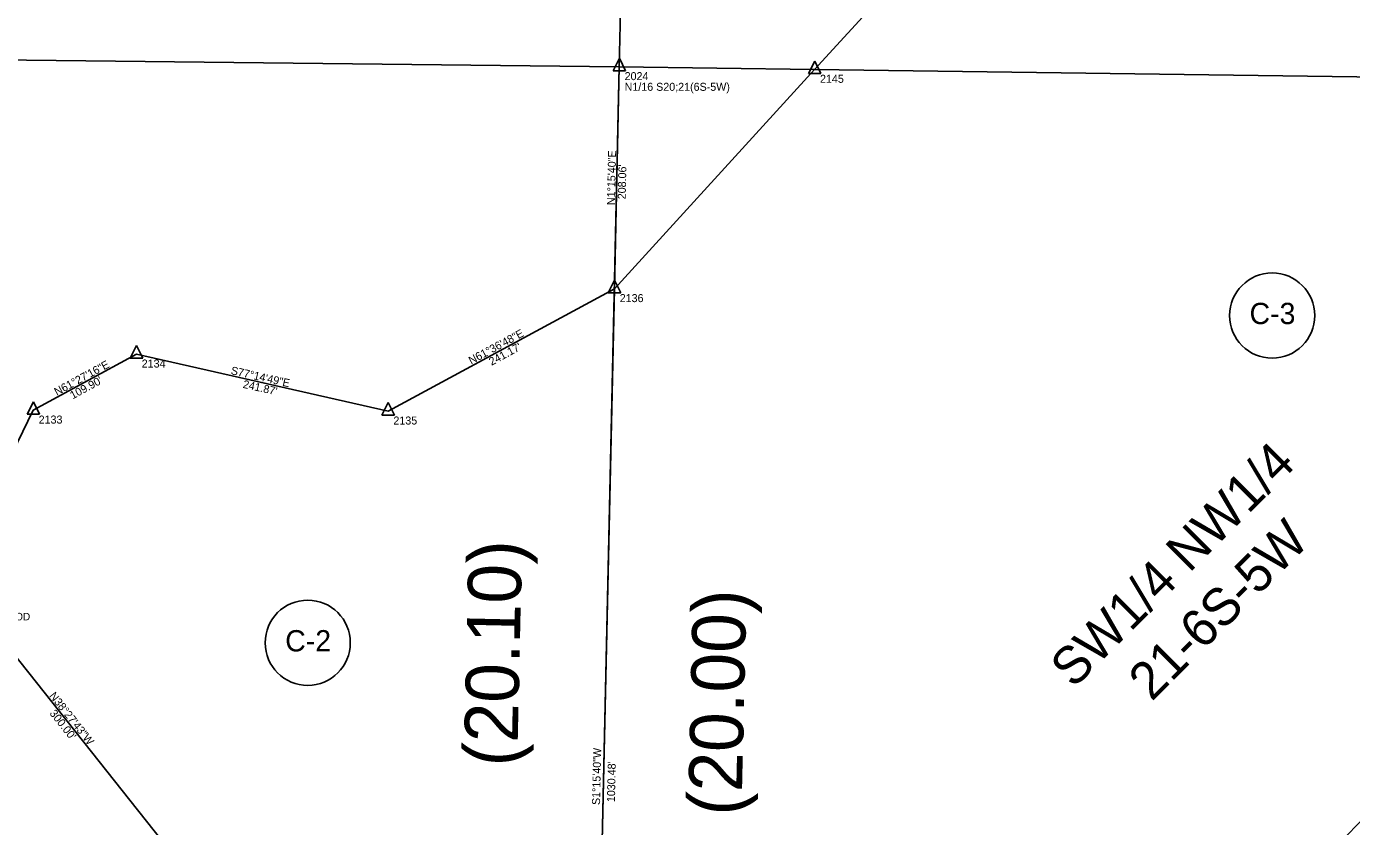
# Model space of a CAD drawing. Extents: x 1431802 to 1457777, y 1852108 to 1876350.
# Drawn here: x 1443202 to 1444444, y 1855549 to 1856299 of the extents above; entities that cross this region are included whole.
import ezdxf

# ---------------------------------------------------------------- set-up
doc = ezdxf.new("R2010")
doc.units = 0
for name, color, linetype in [('S_CAL_CORNER', 7, 'Continuous'), ('S_CAL_CORNER_ANNOT', 7, 'Continuous'), ('S_EXIST_ROW', 7, 'Continuous'), ('S_EXISTING_ALIGNMENT', 7, 'Continuous'), ('S_IRON_PIN_ANNOT', 7, 'Continuous'), ('S_PROPERTY', 7, 'Continuous'), ('S_PROPERTY_ANNOT', 7, 'Continuous'), ('S_SECTION', 7, 'Continuous'), ('S_SECTION_GLO', 7, 'Continuous'), ('S_SECTION_TEXT', 7, 'Continuous'), ('S_SIXTEEN_SECTION', 7, 'Continuous')]:
    doc.layers.add(name, color=color, linetype=linetype)

msp = doc.modelspace()

# ---------------------------------------------------------------- linework, layer by layer
at = {"layer": 'S_CAL_CORNER'}
for p, q in [((1443758.1, 1856269), (1443752.2, 1856257.1)), ((1443758.1, 1856269), (1443752.2, 1856257.1)), ((1443758.1, 1856269), (1443752.2, 1856257.1)), ((1443758.1, 1856269), (1443763.9, 1856257.1)), ((1443758.1, 1856269), (1443763.9, 1856257.1)), ((1443758.1, 1856269), (1443763.9, 1856257.1)), ((1443941.2, 1856266.4), (1443935.3, 1856254.6)), ((1443941.2, 1856266.4), (1443935.3, 1856254.6)), ((1443941.2, 1856266.4), (1443947, 1856254.6)), ((1443941.2, 1856266.4), (1443947, 1856254.6)), ((1443752.2, 1856257.1), (1443763.9, 1856257.1)), ((1443752.2, 1856257.1), (1443763.9, 1856257.1)), ((1443752.2, 1856257.1), (1443763.9, 1856257.1)), ((1443935.3, 1856254.6), (1443947, 1856254.6)), ((1443935.3, 1856254.6), (1443947, 1856254.6)), ((1443753.5, 1856061), (1443747.6, 1856049.1)), ((1443753.5, 1856061), (1443747.6, 1856049.1)), ((1443753.5, 1856061), (1443759.3, 1856049.1)), ((1443753.5, 1856061), (1443759.3, 1856049.1)), ((1443747.6, 1856049.1), (1443759.3, 1856049.1)), ((1443747.6, 1856049.1), (1443759.3, 1856049.1)), ((1443305.5, 1855999.7), (1443299.6, 1855987.9)), ((1443305.5, 1855999.7), (1443311.3, 1855987.9)), ((1443299.6, 1855987.9), (1443311.3, 1855987.9)), ((1443208.9, 1855947.2), (1443203, 1855935.4)), ((1443208.9, 1855947.2), (1443214.7, 1855935.4)), ((1443541.4, 1855946.3), (1443535.5, 1855934.5)), ((1443541.4, 1855946.3), (1443547.2, 1855934.5)), ((1443203, 1855935.4), (1443214.7, 1855935.4)), ((1443535.5, 1855934.5), (1443547.2, 1855934.5))]:
    msp.add_line(p, q, dxfattribs=at)
at = {"layer": 'S_EXIST_ROW'}
for radius, end in [(2914.8, 139.6489), (2814.8, 139.649)]:
    msp.add_arc((1446514.4, 1853493.3), radius, 129.899, end, dxfattribs=at)
at = {"layer": 'S_EXISTING_ALIGNMENT'}
msp.add_arc((1446514.4, 1853493.3), 2864.8, 129.899, 139.649, dxfattribs=at)
at = {"layer": 'S_PROPERTY'}
for p, q in [((1443758, 1856261), (1443787.1, 1857581.1)), ((1443758, 1856261), (1443787.1, 1857581.1)), ((1444008.7, 1856332.5), (1443941.1, 1856258.5)), ((1443753.4, 1856053), (1443758, 1856261)), ((1443753.4, 1856053), (1443758, 1856261)), ((1443941.1, 1856258.5), (1443753.4, 1856053)), ((1443541.3, 1855938.3), (1443753.4, 1856053)), ((1443753.4, 1856053), (1443728.9, 1854940.9)), ((1443753.4, 1856053), (1443730.8, 1855022.7)), ((1443208.8, 1855939.2), (1443305.4, 1855991.7)), ((1443305.4, 1855991.7), (1443541.3, 1855938.3)), ((1443166.9, 1855853.4), (1443208.8, 1855939.2)), ((1443336.5, 1855526.9), (1443149.9, 1855761.8))]:
    msp.add_line(p, q, dxfattribs=at)
for centre in [(1444369.9, 1856027.9), (1443466, 1855721.3)]:
    msp.add_circle(centre, 39.9, dxfattribs=at)
at = {"layer": 'S_SECTION'}
msp.add_line((1443728.9, 1854940.9), (1443758, 1856261), dxfattribs=at)
at = {"layer": 'S_SIXTEEN_SECTION'}
for p, q in [((1442459.3, 1856275.8), (1443758, 1856261)), ((1443758, 1856261), (1443941.1, 1856258.5)), ((1443941.1, 1856258.5), (1445091.4, 1856242.6))]:
    msp.add_line(p, q, dxfattribs=at)

# ---------------------------------------------------------------- texts
at = {"layer": 'S_CAL_CORNER_ANNOT'}
for s, p in [('2024', (1443763, 1856248.5)), ('2145', (1443946.1, 1856246)), ('N1/16 S20;21(6S-5W)', (1443763, 1856238.5)), ('2136', (1443758.4, 1856040.5)), ('2134', (1443310.4, 1855979.2)), ('2133', (1443213.8, 1855926.7)), ('2135', (1443546.3, 1855925.8))]:
    msp.add_text(s, height=7.5, dxfattribs=at).set_placement(p)
at = {"layer": 'S_IRON_PIN_ANNOT'}
msp.add_text('3/4IN IN OD', height=7, dxfattribs=at).set_placement((1443154.9, 1855742.3))
at = {"layer": 'S_PROPERTY'}
for s, p in [('C-3', (1444348.7, 1856019.9)), ('C-2', (1443444.9, 1855713.2))]:
    msp.add_text(s, height=19.95, dxfattribs=at).set_placement(p)
at = {"layer": 'S_PROPERTY_ANNOT'}
for s, rotation, p in [('N1%%d15\'40"E', 88.7388, (1443753.9, 1856131.3)), ("208.06'", 88.7388, (1443764, 1856136.8)), ('N61%%d36\'48"E', 28.3868, (1443619.2, 1855981.9)), ("241.17'", 28.3868, (1443638.3, 1855980.8)), ('N61%%d27\'16"E', 28.5456, (1443230.9, 1855952.6)), ('S77%%d14\'49"E', 347.247, (1443393.4, 1855973.1)), ("109.90'", 28.5456, (1443245.7, 1855949.3)), ("241.87'", 347.247, (1443404.7, 1855960.3)), ('N38%%d27\'43"W', 308.4619, (1443223.3, 1855671.4)), ("300.00'", 308.4619, (1443223.6, 1855655)), ('S1%%d15\'40"W', 88.7388, (1443739.9, 1855569.2)), ("1030.48'", 88.7388, (1443753.9, 1855571.9))]:
    msp.add_text(s, height=7.5, rotation=rotation, dxfattribs=at).set_placement(p)
at = {"layer": 'S_SECTION_GLO'}
for s, p in [('(20.10)', (1443662.3, 1855605.1)), ('(20.00)', (1443872.5, 1855559))]:
    msp.add_text(s, height=50, rotation=88.7389, dxfattribs=at).set_placement(p)
at = {"layer": 'S_SECTION_TEXT'}
for s, p in [('SW1/4 NW1/4', (1444183.7, 1855677.7)), ('21-6S-5W', (1444257, 1855665.7))]:
    msp.add_text(s, height=35, rotation=45, dxfattribs=at).set_placement(p)

doc.saveas('drawing.dxf')
